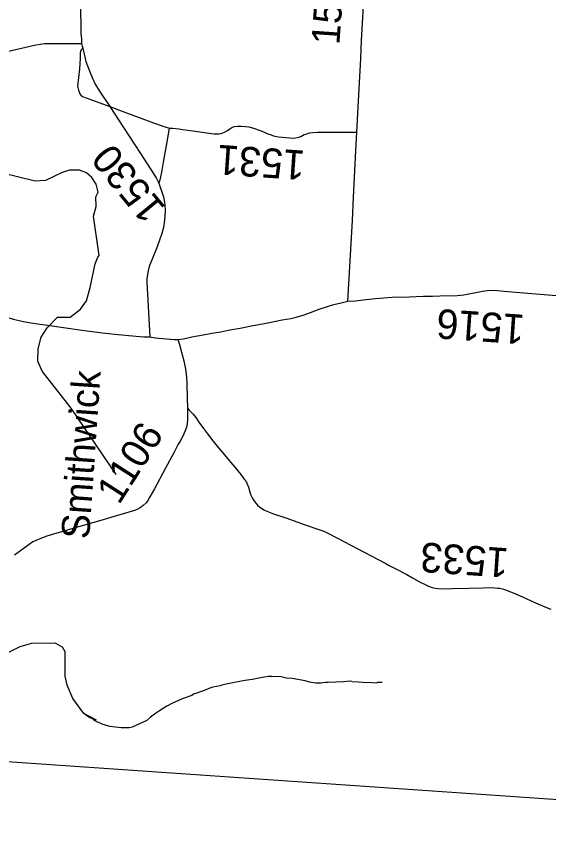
# Model space of a CAD drawing. Extents: x 2598107 to 2605763, y 726018 to 731166.
# Drawn here: x 2598437.8 to 2598627.7, y 727867.1 to 728163.4 of the extents above; entities that cross this region are included whole.
import ezdxf

# ---------------------------------------------------------------- set-up
doc = ezdxf.new("R2010")
doc.units = 0
for name, color, linetype in [('Old_Level_1', 7, 'Continuous'), ('Old_Level_32', 7, 'Continuous'), ('Old_Level_59', 7, 'Continuous')]:
    doc.layers.add(name, color=color, linetype=linetype)

msp = doc.modelspace()

# ---------------------------------------------------------------- linework, layer by layer
at = {"layer": 'Old_Level_1'}
msp.add_line((2598275.57, 727908.37), (2598874.28, 727867.14), dxfattribs=at)
at = {"layer": 'Old_Level_32'}
for points in [[(2598559.29, 728122.22), (2598559.98, 728135.45), (2598560.66, 728148.5), (2598560.98, 728154.91), (2598561.4, 728163.09), (2598561.87, 728171.26), (2598562.96, 728192.44), (2598563.42, 728200.86), (2598563.79, 728208.96), (2598564.19, 728221.46), (2598564.58, 728229.58), (2598565.59, 728251.7)], [(2598460.08, 728195.46), (2598459.97, 728192.59), (2598460.17, 728185.68), (2598460.33, 728178.31), (2598460.33, 728174.75), (2598460.6, 728168.11), (2598460.56, 728164.51), (2598460.68, 728161.02), (2598460.76, 728157.42), (2598461.01, 728155.43), (2598461.02, 728153.88)], [(2598420.49, 728147.72), (2598444.63, 728153.31), (2598447.71, 728153.84), (2598450.73, 728153.87), (2598461.02, 728153.88)], [(2598461.02, 728153.88), (2598461.25, 728152.87), (2598461.42, 728152.17)], [(2598461.42, 728152.17), (2598460.9, 728151.62), (2598460.61, 728150.96), (2598460.5, 728150.36), (2598460.54, 728148.44), (2598460.2, 728144.77), (2598459.57, 728138.66), (2598459.85, 728137.22), (2598460, 728136.9)], [(2598461.42, 728152.17), (2598462.56, 728147.45), (2598463.89, 728143.73), (2598464.74, 728141.64), (2598465.91, 728139.33), (2598467.43, 728136.84), (2598471.08, 728131.33)], [(2598460, 728136.9), (2598460.42, 728135.87), (2598460.77, 728135.34), (2598461.3, 728134.93), (2598462.61, 728134.39), (2598471.08, 728131.33)], [(2598471.08, 728131.33), (2598475.99, 728123.79), (2598481.99, 728114.58), (2598486.82, 728107.19), (2598487.75, 728105.66), (2598488.58, 728104.02)], [(2598471.08, 728131.33), (2598477.07, 728129.04), (2598481.61, 728127.39), (2598486.63, 728125.53), (2598489.01, 728124.7), (2598490.02, 728124.33), (2598492.36, 728123.64)], [(2598488.58, 728104.02), (2598489.09, 728105.19), (2598489.65, 728107.91), (2598490.29, 728111.49), (2598491.41, 728118.02), (2598492.36, 728123.64)], [(2598492.36, 728123.64), (2598493.45, 728123.64), (2598495.69, 728123.34), (2598497.15, 728123.17), (2598500.73, 728122.64), (2598508.17, 728121.6), (2598510.02, 728121.59), (2598510.81, 728121.75), (2598512.04, 728122.19), (2598513.1, 728122.78), (2598513.99, 728123.37), (2598514.64, 728123.79), (2598515.48, 728124.18), (2598516.65, 728124.36), (2598518.03, 728124.32), (2598519.56, 728124.22), (2598520.74, 728124.07), (2598522, 728123.74), (2598525.08, 728122.62), (2598527.55, 728121.6), (2598528.72, 728121.2), (2598529.22, 728120.98), (2598530, 728120.72), (2598531.3, 728120.48), (2598535.28, 728120.12), (2598536.61, 728120.04), (2598537.54, 728120.15), (2598538.58, 728120.37), (2598539.27, 728120.61), (2598539.92, 728120.94), (2598540.5, 728121.3), (2598541.42, 728121.64), (2598542.38, 728121.88), (2598543.58, 728122.09), (2598545.24, 728122.16), (2598547.66, 728122.17), (2598549.83, 728122.17), (2598554.53, 728122.2), (2598557.48, 728122.17), (2598559.29, 728122.22)], [(2598556.11, 728061.82), (2598557.69, 728090.61), (2598558.07, 728099.02), (2598558.91, 728115.53), (2598559.29, 728122.22)], [(2598488.58, 728104.02), (2598490.21, 728099.04), (2598490.77, 728096.31), (2598490.82, 728093.95), (2598490.66, 728090.76), (2598490.19, 728088.12), (2598489.69, 728085.98), (2598488.88, 728083.57), (2598487.76, 728080.59), (2598485.17, 728074.2), (2598484.75, 728072.65), (2598484.29, 728069.96), (2598484.29, 728068.66), (2598485.32, 728049.08)], [(2598556.11, 728061.82), (2598558.77, 728061.99), (2598562.67, 728062.41), (2598565.99, 728062.74), (2598571.85, 728063.25), (2598578.01, 728063.42), (2598583.08, 728063.57), (2598586.24, 728063.63), (2598588.9, 728063.74), (2598595.06, 728063.87), (2598597.46, 728064.09), (2598604.19, 728065.39), (2598605.86, 728065.61), (2598608.11, 728065.71), (2598613.2, 728065.31), (2598633.26, 728063.66)], [(2598495.37, 728048.1), (2598497.38, 728048.37), (2598500.42, 728049.06), (2598504.4, 728049.78), (2598507.45, 728050.36), (2598510.67, 728050.89), (2598513.95, 728051.56), (2598517.58, 728052.21), (2598521.68, 728053.08), (2598527.46, 728054.13), (2598532.61, 728055.15), (2598535.72, 728055.68), (2598537.57, 728056.13), (2598540.5, 728056.99), (2598542.68, 728057.78), (2598545.82, 728058.94), (2598548.78, 728059.93), (2598551.1, 728060.66), (2598553.67, 728061.28), (2598554.61, 728061.47), (2598556.11, 728061.82)], [(2598420.17, 728059.97), (2598428.41, 728057.71), (2598432.58, 728056.59), (2598434.56, 728056.03), (2598436.65, 728055.41), (2598439.61, 728054.72), (2598442.91, 728054.13), (2598445.43, 728053.7), (2598448.82, 728053.21), (2598454.51, 728052.39), (2598461.06, 728051.53), (2598469.48, 728050.38), (2598474.07, 728049.97), (2598479.21, 728049.49), (2598483.27, 728049.1), (2598485.32, 728049.08)], [(2598485.32, 728049.08), (2598487.24, 728048.79), (2598494.03, 728048.13), (2598495.37, 728048.1)], [(2598495.37, 728048.1), (2598495.99, 728046.33), (2598496.72, 728043.62), (2598497.46, 728040.48), (2598498.05, 728037.51), (2598498.41, 728034.86), (2598498.59, 728032.19), (2598498.7, 728027.3), (2598498.76, 728023.68)], [(2598498.76, 728023.68), (2598498.8, 728019.56), (2598498.67, 728018.04), (2598498.44, 728016.86), (2598498.01, 728015.53), (2598497.54, 728014.42), (2598496.98, 728013.39), (2598496.16, 728011.79), (2598495.52, 728010.77), (2598493.88, 728007.7), (2598490.96, 728002.18), (2598487.06, 727994.79), (2598485.42, 727991.94), (2598484.68, 727990.7), (2598484.03, 727989.87), (2598483.03, 727988.83), (2598482.43, 727988.42), (2598481.7, 727987.96), (2598480.83, 727987.44), (2598479.89, 727987.05), (2598476.69, 727986.15), (2598472.64, 727984.92), (2598467.93, 727983.54), (2598461.58, 727981.71), (2598451.03, 727978.64), (2598448.65, 727977.91), (2598447.02, 727977.29), (2598445.28, 727976.66), (2598443.64, 727975.84), (2598440.96, 727973.97), (2598437.03, 727971.15)], [(2598498.76, 728023.68), (2598499.45, 728022.95), (2598500.87, 728021.46), (2598501.77, 728020.24), (2598502.88, 728018.67), (2598504.53, 728016.34), (2598505.93, 728014.43), (2598507.85, 728011.98), (2598509.89, 728009.51), (2598511.97, 728007.01), (2598514.28, 728004.23), (2598515.67, 728002.6), (2598517.89, 727999.96), (2598519.08, 727998.32), (2598519.6, 727997.62), (2598519.98, 727996.86), (2598520.54, 727995.36), (2598521.07, 727993.6), (2598521.47, 727992.56), (2598521.87, 727991.65), (2598522.53, 727990.62), (2598523.16, 727989.73), (2598523.81, 727989.03), (2598524.51, 727988.34), (2598526.09, 727987.34), (2598527.18, 727986.83), (2598529.53, 727985.92), (2598533.89, 727984.45), (2598536.92, 727983.38), (2598540.5, 727982.13), (2598546.06, 727980.18), (2598547.15, 727979.81), (2598547.95, 727979.44), (2598548.9, 727979), (2598552.39, 727977.21), (2598561.94, 727972.17), (2598566.7, 727969.7), (2598569.62, 727968.18), (2598570.61, 727967.62), (2598573.18, 727966.3), (2598577.19, 727964.17), (2598579.16, 727963), (2598581.94, 727961.52), (2598583.44, 727960.76), (2598584.85, 727960.04), (2598586.16, 727959.61), (2598587.3, 727959.34), (2598588.37, 727959.19), (2598590.15, 727959.16), (2598593.36, 727959.22), (2598599.31, 727959.36), (2598604.39, 727959.5), (2598607.14, 727959.53), (2598608.57, 727959.5), (2598609.67, 727959.4), (2598610.17, 727959.33), (2598611.3, 727959.1), (2598612.38, 727958.7), (2598615.1, 727957.64), (2598618.4, 727956.23), (2598623.13, 727954.13), (2598626.45, 727952.73), (2598628.54, 727951.81)]]:
    msp.add_lwpolyline(points, dxfattribs=at)
at = {"layer": 'Old_Level_59'}
msp.add_line((2598466.36, 727912.16), (2598461.84, 727914.64), dxfattribs=at)
for points in [[(2598466.93, 728100.74), (2598466.21, 728103.56), (2598464.65, 728106.03), (2598462.73, 728107.63), (2598460.27, 728108.63), (2598456.71, 728108.66), (2598454.01, 728107.79), (2598448.15, 728104.93), (2598444.44, 728104.73), (2598432.8, 728107.55), (2598431.28, 728108.5)], [(2598467.32, 728078.08), (2598465.26, 728092.15), (2598466.16, 728095.63), (2598466.13, 728099.03), (2598466.93, 728100.74)], [(2598473.29, 727999.91), (2598457.31, 728023.58), (2598446.97, 728036.79), (2598445.39, 728040.38), (2598445.48, 728044.78), (2598446.55, 728049.01), (2598448.71, 728052.3), (2598452.39, 728056.16), (2598456.89, 728056.06), (2598460.64, 728059.02), (2598462.7, 728061.95), (2598464.11, 728066.66), (2598465.87, 728075.13), (2598466.83, 728077.6), (2598467.32, 728078.08)], [(2598461.84, 727914.64), (2598457.83, 727919.99), (2598455.82, 727924.74), (2598455.11, 727927.92), (2598455.1, 727936.62), (2598454.21, 727938.3), (2598451.53, 727939.67), (2598443.09, 727939.57), (2598438.97, 727938.39), (2598431.64, 727934.85)], [(2598557.44, 727926.07), (2598556.78, 727926.13), (2598554.57, 727925.88), (2598549.01, 727925.69), (2598548.06, 727925.62), (2598546.42, 727925.45), (2598544.61, 727925.45), (2598542.32, 727925.77), (2598540.82, 727926.26), (2598536.2, 727927.09), (2598534.18, 727927.22), (2598532.25, 727927.67), (2598528.88, 727927.81), (2598528.51, 727927.76), (2598527.59, 727927.81), (2598526.32, 727927.51), (2598524.25, 727927.19), (2598522.07, 727926.72), (2598519.25, 727926.34), (2598513.21, 727925.18), (2598511.1, 727924.76), (2598510.52, 727924.49), (2598507.89, 727923.96), (2598506.49, 727923.51), (2598505.15, 727922.91), (2598501.82, 727921.71), (2598501.21, 727921.56), (2598500.39, 727921.08), (2598496.95, 727919.86), (2598496.48, 727919.55), (2598493.41, 727918.25), (2598491.41, 727917.26), (2598488.84, 727915.6), (2598487.03, 727914.3), (2598485.66, 727913.28), (2598484.34, 727912.07), (2598479.07, 727909.73), (2598478.03, 727909.51), (2598475.17, 727909.52), (2598471.1, 727910), (2598468.37, 727910.79), (2598467.11, 727911.39), (2598466.66, 727911.56)], [(2598557.44, 727926.07), (2598559.84, 727925.92), (2598561.35, 727925.79), (2598564.74, 727925.63), (2598566.23, 727925.56), (2598566.78, 727925.74), (2598568.32, 727925.73)], [(2598466.66, 727911.56), (2598465.66, 727912.15), (2598465.42, 727912.41), (2598463.88, 727913.21), (2598463.21, 727913.51), (2598461.84, 727914.64)]]:
    msp.add_lwpolyline(points, dxfattribs=at)

# ---------------------------------------------------------------- texts
at = {"layer": 'Old_Level_1'}
for s, height, rotation, p in [('1535', 10.003, 86.0601, (2598553.04, 728153.19)), ('1530', 10.285, 129.5119, (2598491.34, 728095.19)), ('1531', 10.559, 176.0601, (2598541.1, 728115.53)), ('1516', 10.559, 176.0601, (2598619.48, 728056.93)), ('Smithwick', 10.003, 86.0601, (2598463.7, 727976.68)), ('1106', 10.145, 57.3831, (2598474.35, 727988.83)), ('1533', 10.559, 176.0601, (2598613.74, 727973.57))]:
    msp.add_text(s, height=height, rotation=rotation, dxfattribs=at).set_placement(p)

doc.saveas('drawing.dxf')
